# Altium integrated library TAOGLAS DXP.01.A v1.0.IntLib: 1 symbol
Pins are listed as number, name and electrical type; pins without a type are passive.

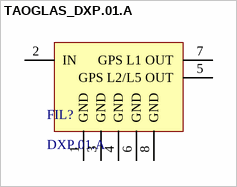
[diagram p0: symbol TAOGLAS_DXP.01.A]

## TAOGLAS_DXP.01.A
designator FIL?, comment DXP.01.A
SMD L1/L2 SAW Diplexer For GPS/GALILEO L1, GLONASS L2 & BeiDou B2; ComponentLibStatus: Created; MFG: Taoglas; Temp_High: +85C; Temp_Low: -40C
footprint TAOGLAS_DXP.01.A (SMD L1/L2 SAW Diplexer For GPS/GALILEO L1, GLONASS L2 & BeiDou B2)
pins: 1 GND, 2 IN, 3 GND, 4 GND, 5 GPS L2/L5 OUT, 6 GND, 7 GPS L1 OUT, 8 GND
